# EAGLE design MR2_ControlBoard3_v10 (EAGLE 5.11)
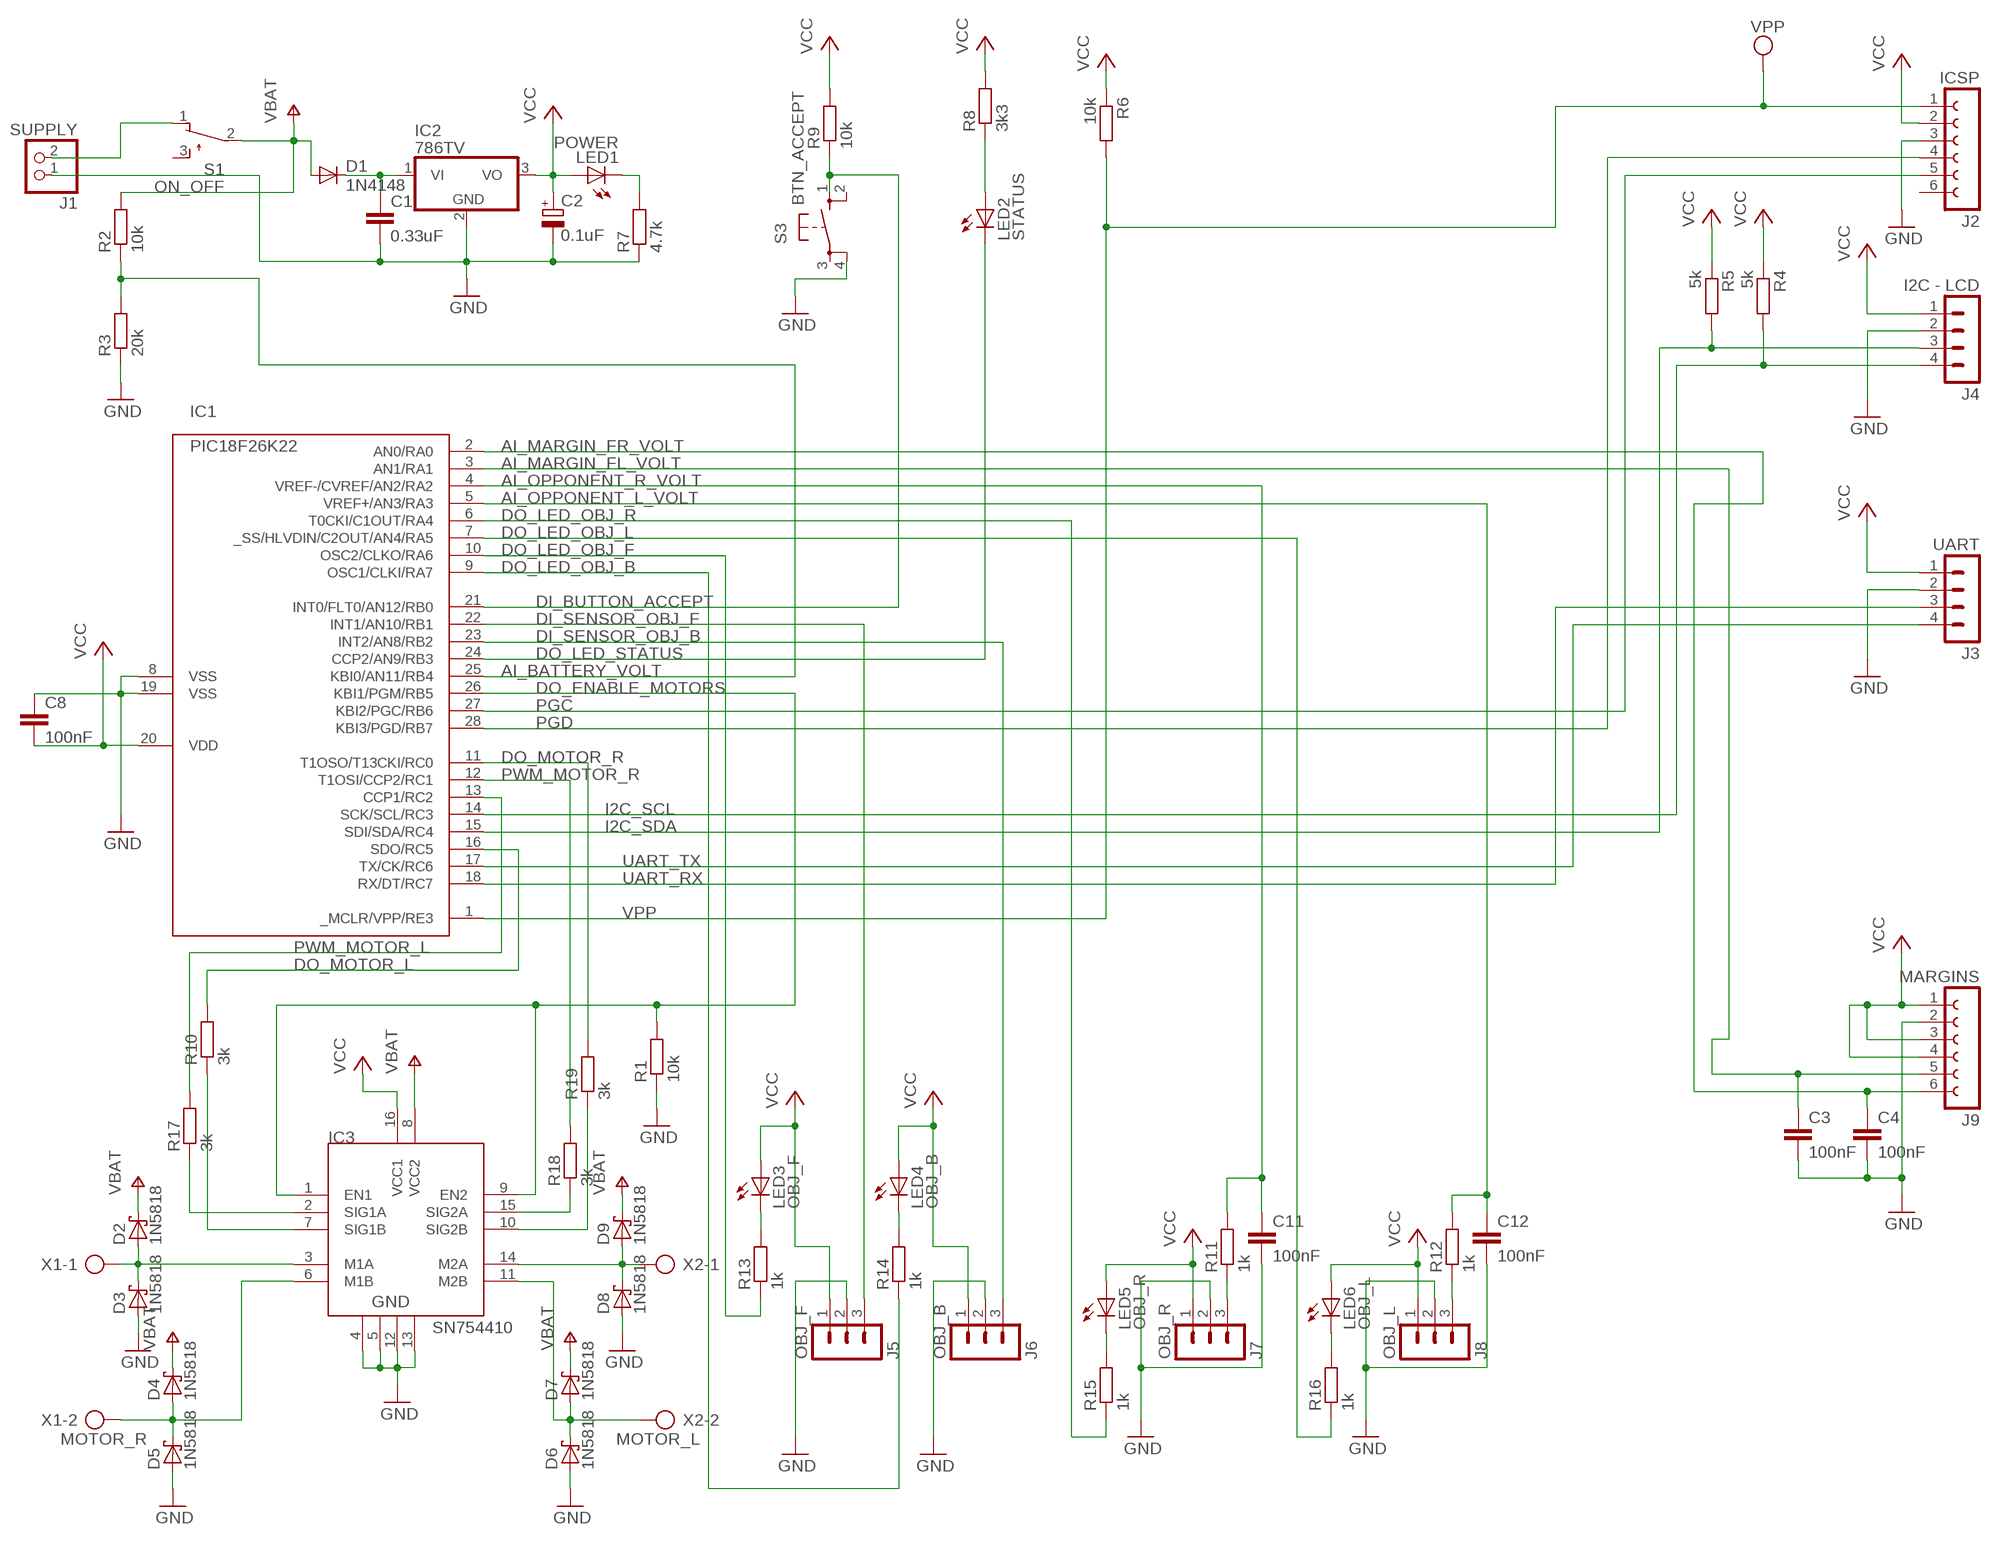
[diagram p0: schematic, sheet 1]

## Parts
C1  0.33uF  C-EU075-052X106  [C075-052X106]
C2  0.1uF  CPOL-EUE2,5-6E  [E2,5-6E]
C3  100nF  C-EU025-024X044  [C025-024X044]
C4  100nF  C-EU025-024X044  [C025-024X044]
C8  100nF  C-EU025-024X044  [C025-024X044]
C11  100nF  C-EU025-024X044  [C025-024X044]
C12  100nF  C-EU025-024X044  [C025-024X044]
D1  1N4148  1N4148DO35-7  [DO35-7]
D2  1N5818  1N5818-T  [DO41-7.6]
D3  1N5818  1N5818-T  [DO41-7.6]
D4  1N5818  1N5818-T  [DO41-7.6]
D5  1N5818  1N5818-T  [DO41-7.6]
D6  1N5818  1N5818-T  [DO41-7.6]
D7  1N5818  1N5818-T  [DO41-7.6]
D8  1N5818  1N5818-T  [DO41-7.6]
D9  1N5818  1N5818-T  [DO41-7.6]
IC1  PIC18F26K22  PIC18F2420-I/SP  [DIL28-3]
IC2  786TV  [TO220V]
IC3  SN754410  [DIP16]
J1  SUPPLY  PINHD-1X2  [1X02]
J2  ICSP  FE06-1  [FE06]
J3  UART  MA04-1  [MA04-1]
J4  I2C - LCD  MA04-1  [MA04-1]
J5  OBJ_F  MA03-1  [MA03-1]
J6  OBJ_B  MA03-1  [MA03-1]
J7  OBJ_R  MA03-1  [MA03-1]
J8  OBJ_L  MA03-1  [MA03-1]
J9  MARGINS  FE06-1  [FE06]
LED1  POWER  LED3MM  [LED3MM]
LED2  STATUS  LED3MM  [LED3MM]
LED3  OBJ_F  LED3MM  [LED3MM]
LED4  OBJ_B  LED3MM  [LED3MM]
LED5  OBJ_R  LED3MM  [LED3MM]
LED6  OBJ_L  LED3MM  [LED3MM]
R1  10k  R-EU_0204/7  [0204/7]
R2  10k  R-EU_0204/7  [0204/7]
R3  20k  R-EU_0204/7  [0204/7]
R4  5k  R-EU_0207/2V  [0207/2V]
R5  5k  R-EU_0207/2V  [0207/2V]
R6  10k  R-EU_0204/7  [0204/7]
R7  4.7k  R-EU_0204/7  [0204/7]
R8  3k3  R-EU_0204/7  [0204/7]
R9  10k  R-EU_0204/7  [0204/7]
R10  3k  R-EU_0204/7  [0204/7]
R11  1k  R-EU_0207/7  [0207/7]
R12  1k  R-EU_0207/7  [0207/7]
R13  1k  R-EU_0204/7  [0204/7]
R14  1k  R-EU_0204/7  [0204/7]
R15  1k  R-EU_0207/2V  [0207/2V]
R16  1k  R-EU_0207/2V  [0207/2V]
R17  3k  R-EU_0204/7  [0204/7]
R18  3k  R-EU_0204/7  [0204/7]
R19  3k  R-EU_0204/7  [0204/7]
S1  ON_OFF  TL32PO  [TL3XPO]
S3  BTN_ACCEPT  10XX  [B3F-10XX]
X1  MOTOR_R  AK500/2  [AK500/2]
X2  MOTOR_L  AK500/2  [AK500/2]

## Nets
AI_BATTERY_VOLT: IC1.25(KBI0/AN11/RB4) R2.1 R3.2
AI_MARGIN_FL_VOLT: C3.1 IC1.3(AN1/RA1) J9.5
AI_MARGIN_FR_VOLT: C4.1 IC1.2(AN0/RA0) J9.6
AI_OPPONENT_L_VOLT: C12.1 IC1.5(VREF+/AN3/RA3) R12.2
AI_OPPONENT_R_VOLT: C11.1 IC1.4(VREF-/CVREF/AN2/RA2) R11.2
DI_BUTTON_ACCEPT: IC1.21(INT0/FLT0/AN12/RB0) R9.1 S3.1
DI_SENSOR_OBJ_B: IC1.23(INT2/AN8/RB2) J6.3
DI_SENSOR_OBJ_F: IC1.22(INT1/AN10/RB1) J5.3
DO_ENABLE_MOTORS: IC1.26(KBI1/PGM/RB5) IC3.1(EN1) IC3.9(EN2) R1.2
DO_LED_OBJ_B: IC1.9(OSC1/CLKI/RA7) R14.1
DO_LED_OBJ_F: IC1.10(OSC2/CLKO/RA6) R13.1
DO_LED_OBJ_L: IC1.7(_SS/HLVDIN/C2OUT/AN4/RA5) R16.1
DO_LED_OBJ_R: IC1.6(T0CKI/C1OUT/RA4) R15.1
DO_LED_STATUS: IC1.24(CCP2/AN9/RB3) LED2.K(C)
DO_MOTOR_L: IC1.16(SDO/RC5) R10.2
DO_MOTOR_R: IC1.11(T1OSO/T13CKI/RC0) R19.2
GND: C1.2 C2.- C3.2 C4.2 C8.1 C11.2 C12.2 D3.A D5.A D6.A D8.A IC1.8(VSS) IC1.19(VSS) IC2.2(GND) IC3.4 IC3.5 IC3.12 IC3.13 J1.1 J2.3 J3.2 J4.2 J5.2 J6.2 J7.2 J8.2 J9.2 R1.1 R3.1 R7.1 S3.4
I2C_SCL: IC1.14(SCK/SCL/RC3) J4.4 R4.2
I2C_SDA: IC1.15(SDI/SDA/RC4) J4.3 R5.2
N$1: IC3.2(SIG1A) R17.1
N$2: C1.1 D1.C IC2.1(VI)
N$3: J7.3 R11.1
N$5: IC3.7(SIG1B) R10.1
N$6: LED1.K(C) R7.2
N$7: IC3.15(SIG2A) R18.1
N$8: IC3.10(SIG2B) R19.1
N$9: J1.2 S1.1(O)
N$13: LED3.K(C) R13.2
N$16: LED4.K(C) R14.2
N$18: LED5.K(C) R15.2
N$19: LED6.K(C) R16.2
N$21: LED2.A R8.1
N$27: D2.A D3.C IC3.3(M1A) X1.1
N$28: D4.A D5.C IC3.6(M1B) X1.2
N$29: D8.C D9.A IC3.14(M2A) X2.1
N$30: D6.C D7.A IC3.11(M2B) X2.2
N$41: J8.3 R12.1
PGC: IC1.27(KBI2/PGC/RB6) J2.5
PGD: IC1.28(KBI3/PGD/RB7) J2.4
PWM_MOTOR_L: IC1.13(CCP1/RC2) R17.2
PWM_MOTOR_R: IC1.12(T1OSI/CCP2/RC1) R18.2
UART_RX: IC1.18(RX/DT/RC7) J3.3
UART_TX: IC1.17(TX/CK/RC6) J3.4
V+: D1.A D2.C D4.C D7.C D9.C IC3.8(VCC2) R2.2 S1.2(P) ; supply symbol labelled VBAT
VCC: C2.+ C8.2 IC1.20(VDD) IC2.3(VO) IC3.16(VCC1) J2.2 J3.1 J4.1 J5.1 J6.1 J7.1 J8.1 J9.1 J9.3 J9.4 LED1.A LED3.A LED4.A LED5.A LED6.A R4.1 R5.1 R6.1 R8.2 R9.2
VPP: IC1.1(_MCLR/VPP/RE3) J2.1 R6.2
Unconnected: J2.6 S1.3(S) S3.2 S3.3

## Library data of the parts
C1 C3 C4 C8 C11 C12 = rcl:C-EU: CAPACITOR, European symbol
C2 = rcl:CPOL-EU: POLARIZED CAPACITOR, European symbol
D1 = diode:1N4148: DIODE
D2-D9 = diode:1N581*: 1.0A SCHOTTKY BARRIER RECTIFIER
IC1 = pic18fxx20:PIC18*2420: PIC18*2420 Microchip FLASH Microcontroller with A/D DEVICE FEATURES FeaturePIC18*2420 Program Memory (bytes) 16384 Program Memory (instructions) 8192 Interupt Sources 19 I/O Ports Ports A, B, C, (E) Capture/Compare/PWM Modules 2 Enhanced Capture/Compare/PWM Modules 0 Parallel Communications (PSP)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
IC2 = linear:78*: Positive VOLTAGE REGULATOR Source: http://cache.national.com/ds/LM/LM78L05.pdf http://www.fairchildsemi.com/ds/LM/LM7805.pdf
IC3 = HBridge:SN754410: Quadruple half-H driver
J1 = pinhead:PINHD-1X2: PIN HEADER
J2 J9 = con-lsta:FE06-1: FEMALE HEADER
J3 J4 = con-lstb:MA04-1: PIN HEADER
J5-J8 = con-lstb:MA03-1: PIN HEADER
LED1-LED6 = led:LED: LED
R1-R19 = rcl:R-EU_: RESISTOR, European symbol
S1 = switch:TL32PO: TINY SWITCH ON - MOM Source: http://www2.produktinfo.conrad.com/datenblaetter/700000-724999/705152-da-01-de-Subminiaturschalter_TL_36YO.pdf
S3 = KEY_B:10XX
X1 X2 = con-ptr500:AK500/2: CONNECTOR

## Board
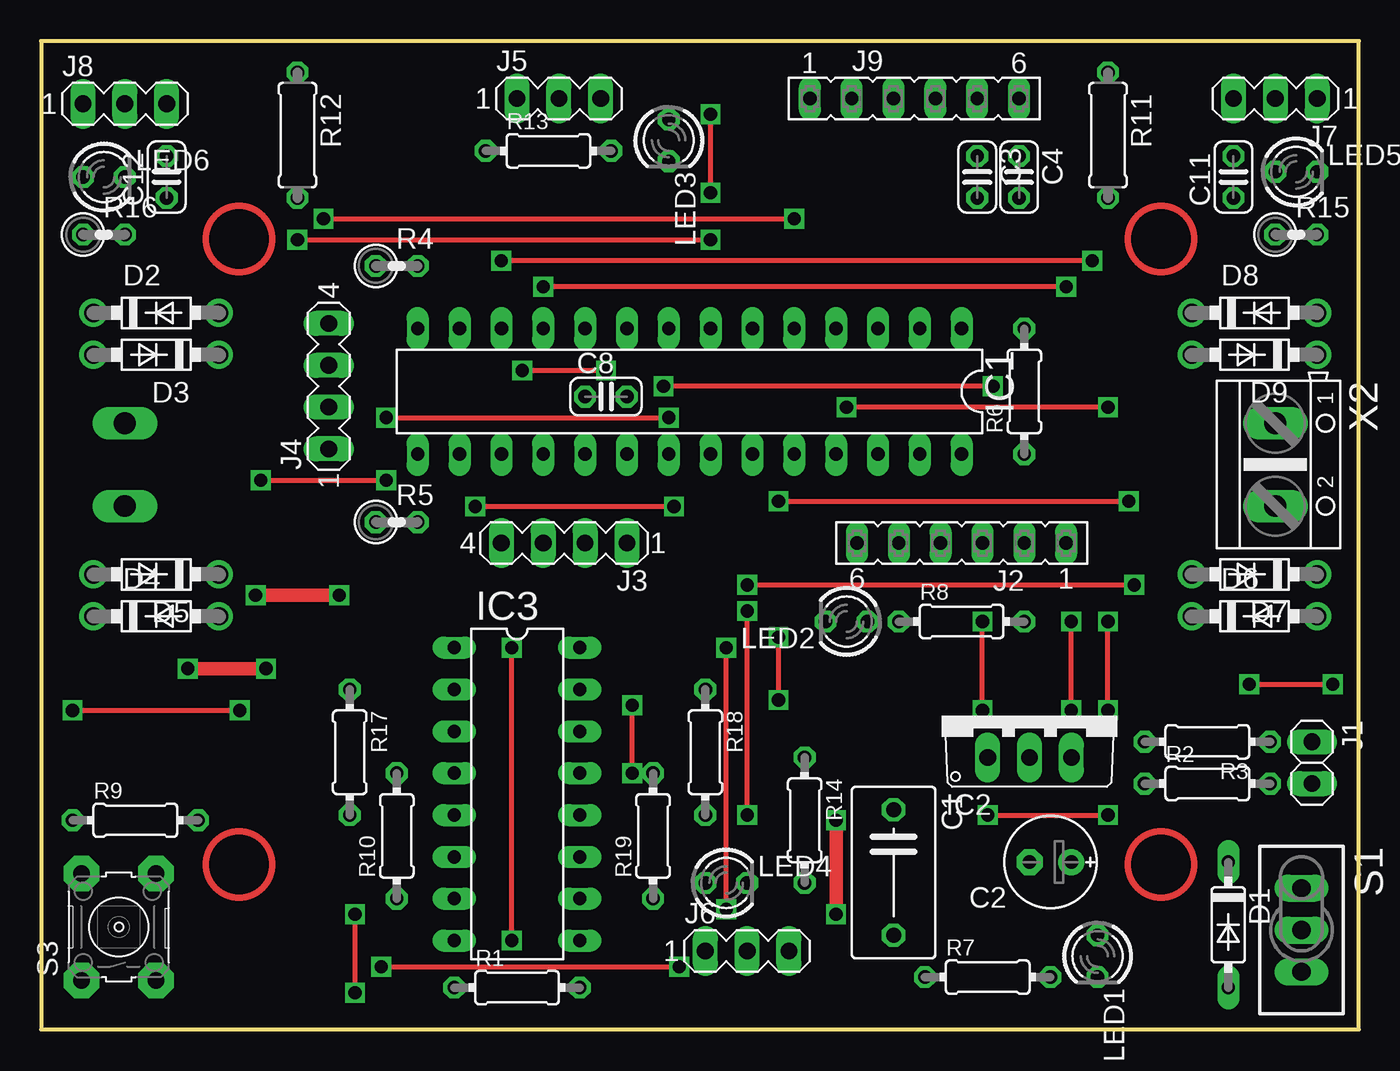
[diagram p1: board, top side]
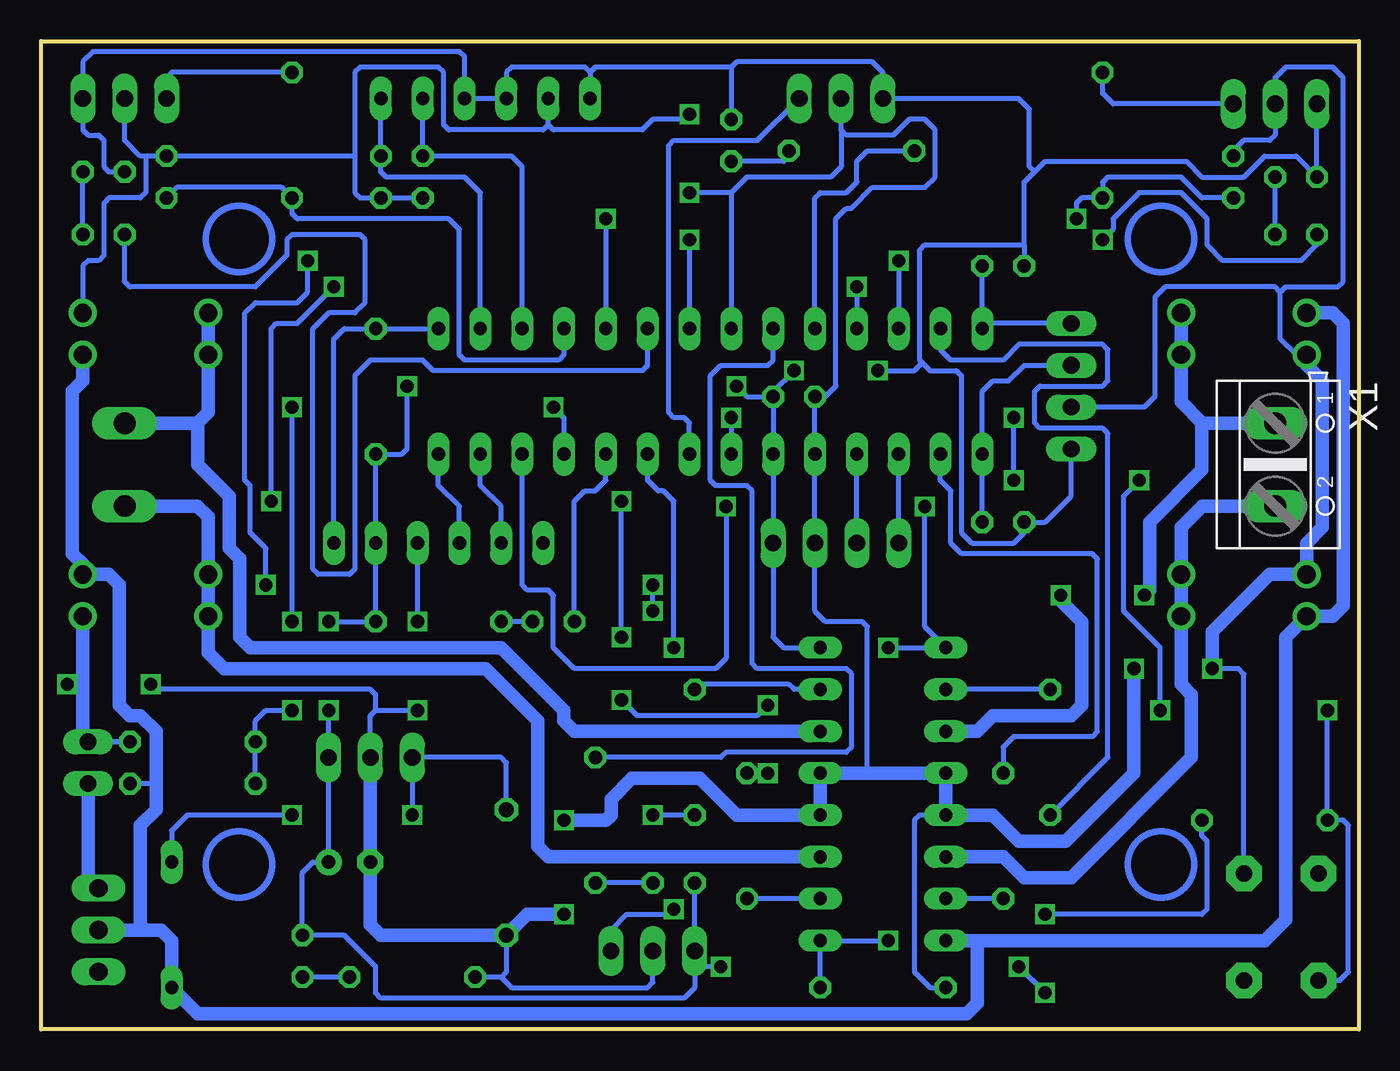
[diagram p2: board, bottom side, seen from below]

Size 80 x 60 mm. Coordinates in mm from the lower left corner, seen from the top.
Outline: 0,0 80,0 80,60 0,60 0,0
Copper layers (1*16): Top 0.035mm / dielectric 1.5mm / Bottom 0.035mm
Design rules "default *": minimum track width 12mil, minimum drill 24mil, track to track 12mil, track to pad 12mil, pad to pad 12mil, via to via 12mil, smd to smd 8mil, copper to edge 40mil, drill to drill 8mil, minimum pad ring 10mil, minimum via ring 8mil, stop-mask expansion 4mil, vias tented up to drill 0mil, thermal gap 10mil

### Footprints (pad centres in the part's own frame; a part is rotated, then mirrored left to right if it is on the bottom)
C075-052X106 = drill 0.914 octagon: 1 -3.81,0; 2 3.81,0
E2,5-6E = drill 0.813 pad 1.575 round: + -1.27,0 | drill 0.813 pad 1.575 octagon: - 1.27,0
C025-024X044 = drill 0.813 octagon: 1 -1.27,0; 2 1.27,0
DO35-7 = drill 0.813 long: A 3.81,0; C -3.81,0
DO41-7.6 = drill 1.1 pad 1.7 round: A 3.81,0; C -3.81,0
DIL28-3 = drill 0.813 long: 1 -16.51,-3.81; 2 -13.97,-3.81; 3 -11.43,-3.81; 4 -8.89,-3.81; 5 -6.35,-3.81; 6 -3.81,-3.81; 7 -1.27,-3.81; 8 1.27,-3.81; 9 3.81,-3.81; 10 6.35,-3.81; 11 8.89,-3.81; 12 11.43,-3.81; 13 13.97,-3.81; 14 16.51,-3.81; 15 16.51,3.81; 16 13.97,3.81; 17 11.43,3.81; 18 8.89,3.81; 19 6.35,3.81; 20 3.81,3.81; 21 1.27,3.81; 22 -1.27,3.81; 23 -3.81,3.81; 24 -6.35,3.81; 25 -8.89,3.81; 26 -11.43,3.81; 27 -13.97,3.81; 28 -16.51,3.81
TO220V = drill 1.016 long: 1 -2.54,-2.54; 2 0,-2.54; 3 2.54,-2.54
DIP16 = drill 0.813 long: 1 -10.16,-3.81; 2 -7.62,-3.81; 3 -5.08,-3.81; 4 -2.54,-3.81; 5 0,-3.81; 6 2.54,-3.81; 7 5.08,-3.81; 8 7.62,-3.81; 9 7.62,3.81; 10 5.08,3.81; 11 2.54,3.81; 12 0,3.81; 13 -2.54,3.81; 14 -5.08,3.81; 15 -7.62,3.81; 16 -10.16,3.81
1X02 = drill 1.016 long: 1 -1.27,0; 2 1.27,0
FE06 = drill 0.813 long: 1 -6.35,0; 2 -3.81,0; 3 -1.27,0; 4 1.27,0; 5 3.81,0; 6 6.35,0
MA04-1 = drill 1.016 long: 1 -3.81,0; 2 -1.27,0; 3 1.27,0; 4 3.81,0
MA03-1 = drill 1.016 long: 1 -2.54,0; 2 0,0; 3 2.54,0
LED3MM = drill 0.813 octagon: A -1.27,0; K 1.27,0
0204/7 = drill 0.813 octagon: 1 -3.81,0; 2 3.81,0
0207/2V = drill 0.813 octagon: 1 -1.27,0; 2 1.27,0
0207/7 = drill 0.813 octagon: 1 -3.81,0; 2 3.81,0
TL3XPO = drill 1.1 pad 1.422 long: 1 -2.54,0; 2 0,0; 3 2.54,0
B3F-10XX = drill 1.016 pad 2.159 octagon: 1 -3.379,2.312; 2 3.123,2.312; 3 -3.379,-2.209; 4 3.123,-2.209
AK500/2 = drill 1.321 long: 1 -2.515,0; 2 2.515,0

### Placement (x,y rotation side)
C1  51.75,9.53 270 top
C2  61.28,10.16 180 top
C3  56.83,51.75 270 top
C4  59.37,51.75 270 top
C8  34.29,38.42 0 top
C11  72.39,51.75 90 top
C12  7.62,51.75 90 top
D1  72.07,6.35 270 top
D2  6.99,43.5 0 top
D3  6.99,40.96 180 top
D4  6.99,25.08 0 top
D5  6.99,27.62 180 top
D6  73.66,25.08 0 top
D7  73.66,27.62 180 top
D8  73.66,43.5 0 top
D9  73.66,40.96 180 top
IC1  39.37,38.73 180 top
IC2  60.01,19.05 0 top
IC3  28.89,13.02 270 top
J1  77.15,16.19 270 top
J2  55.88,29.53 180 top
J3  31.75,29.53 180 top
J4  17.46,39.05 90 top
J5  31.43,56.52 0 top
J6  42.86,4.76 0 top
J7  74.93,56.52 180 top
J8  5.08,56.2 0 top
J9  53.02,56.52 0 top
LED1  64.14,4.45 270 top
LED2  48.9,24.77 180 top
LED3  38.1,53.98 270 top
LED4  41.59,8.89 0 top
LED5  76.2,52.07 0 top
LED6  3.81,51.75 0 top
R1  28.89,2.54 0 top
R2  70.8,14.92 0 top
R3  70.8,17.46 180 top
R4  21.59,46.35 0 top
R5  21.59,30.8 0 top
R6  59.69,38.73 90 top
R7  57.47,3.17 0 top
R8  55.88,24.77 0 top
R9  5.71,12.7 0 top
R10  21.59,11.75 90 top
R11  64.77,54.29 270 top
R12  15.56,54.29 270 top
R13  30.8,53.34 0 top
R14  46.35,12.7 270 top
R15  76.2,48.26 0 top
R16  3.81,48.26 0 top
R17  18.73,16.83 270 top
R18  40.32,16.83 270 top
R19  37.15,11.75 90 top
S1  76.52,6.03 270 top
S3  4.76,6.35 90 top
X1  5.08,34.29 270 bottom
X2  74.93,34.29 270 top

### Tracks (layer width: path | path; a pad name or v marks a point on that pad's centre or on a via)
AI_BATTERY_VOLT  (via drill 0.8)
  Top 0.305: v64.77,37.78 v48.9,37.78 | v64.77,19.37 v64.77,24.77
  Bottom 0.305: R2.1 R3.2 66.99,18.73 66.36,19.37 v64.77,19.37 | IC1.25 48.26,37.15 v48.9,37.78 | v64.77,24.77 v64.77,37.78
AI_MARGIN_FL_VOLT
  Bottom 0.305: J9.5 C3.1 51.44,53.02 50.8,52.39 IC1.3
AI_MARGIN_FR_VOLT
  Bottom 0.305: J9.6 C4.1 59.37,52.07 59.05,51.75 54.29,51.75 53.34,50.8 IC1.2
AI_OPPONENT_L_VOLT  (via drill 0.8)
  Top 0.305: v17.14,49.21 v45.72,49.21
  Bottom 0.305: v45.72,49.21 IC1.5 | v17.14,49.21 17.14,50.16 16.83,50.48 R12.2 15.56,51.44 15.24,51.75 10.79,51.75 9.53,50.48 C12.1
AI_OPPONENT_R_VOLT
  Bottom 0.305: C11.1 71.75,51.12 65.41,51.12 R11.2 64.77,49.53 64.45,49.21 55.24,49.21 54.61,48.58 54.61,40.96 54.29,40.64 48.58,40.64 48.26,40.96 IC1.4
DI_BUTTON_ACCEPT  (via drill 0.8)
  Top 0.305: v20.95,37.15 v38.1,37.15 | v1.91,19.37 v12.06,19.37 | v13.34,33.34 v20.95,33.34
  Bottom 0.305: S3.1 1.16,2.97 0.64,3.49 0.64,12.38 0.95,12.7 R9.1 v1.91,19.37 | v12.06,19.37 12.06,23.18 14.29,25.4 14.29,32.38 v13.34,33.34 | v20.95,33.34 v20.95,37.15 | v38.1,37.15 IC1.21
DI_SENSOR_OBJ_B  (via drill 0.8)
  Top 0.305: v41.59,7.3 v41.59,23.18
  Bottom 0.305: J6.3 45.4,6.03 44.45,6.99 41.91,6.99 v41.59,7.3 | v41.59,23.18 41.59,32.07 42.23,32.7 42.55,32.7 43.18,33.34 IC1.23
DI_SENSOR_OBJ_F
  Bottom 0.305: J5.3 36.51,53.98 41.59,53.98 41.91,53.66 41.91,37.47 41.59,37.15 40.96,37.15 40.64,36.83 IC1.22
DO_ENABLE_MOTORS  (via drill 0.8)
  Top 0.305: v28.57,5.4 v28.57,23.18 | v26.35,31.75 v38.42,31.75
  Bottom 0.305: R1.2 IC3.9 v28.57,5.4 | v28.57,23.18 IC3.1 26.35,24.45 v26.35,31.75 | IC1.26 50.8,26.99 50.48,26.67 49.21,26.67 48.9,26.35 48.9,23.18 47.62,21.91 39.05,21.91 38.42,22.54 v38.42,31.75
DO_LED_OBJ_B
  Bottom 0.305: R14.1 38.73,16.51 38.42,16.83 31.11,16.83 30.8,17.14 30.8,21.59 31.11,21.91 36.51,21.91 36.83,22.23 36.83,32.7 37.15,33.02 39.05,33.02 39.37,33.34 39.37,39.69 38.73,40.32 35.88,40.32 35.56,40.64 IC1.9
DO_LED_OBJ_F
  Bottom 0.305: R13.1 29.84,53.34 30.48,52.7 30.48,51.44 31.11,50.8 32.7,50.8 33.02,50.48 IC1.10
DO_LED_OBJ_L  (via drill 0.8)
  Top 0.305: v15.56,47.94 v40.64,47.94
  Bottom 0.305: R16.1 2.54,47.62 3.49,46.67 8.26,46.67 9.21,47.62 9.21,49.21 10.79,50.8 13.34,50.8 14.92,49.21 14.92,48.58 v15.56,47.94 | v40.64,47.94 IC1.7
DO_LED_OBJ_R
  Bottom 0.305: IC1.6 43.18,40.32 43.5,40.01 56.2,40.01 56.83,40.64 60.01,40.64 60.96,39.69 60.96,27.94 61.28,27.62 63.18,27.62 63.5,27.94 63.5,42.55 62.55,43.5 60.96,43.5 60.33,44.13 60.33,47.94 60.64,48.26 64.77,48.26 65.09,47.94 65.09,46.99 66.99,45.09 74.61,45.09 74.93,45.4 R15.1
DO_LED_STATUS
  Bottom 0.305: LED2.K 47.62,32.07 46.99,32.7 46.35,32.7 45.72,33.34 IC1.24
DO_MOTOR_L
  Bottom 0.305: R10.2 21.59,17.14 20.95,17.78 16.19,17.78 15.88,18.1 15.88,28.57 16.19,28.89 24.13,28.89 24.77,29.53 24.77,32.7 25.4,33.34 IC1.16
DO_MOTOR_R  (via drill 0.8)
  Top 0.305: v62.23,45.09 v30.48,45.09 | v44.77,32.07 v66.04,32.07 | v44.77,20 v44.77,23.81 | v35.88,15.56 v35.88,19.68
  Bottom 0.305: v30.48,45.09 IC1.11 | v62.23,45.09 64.45,42.86 65.72,42.86 66.04,42.55 v66.04,32.07 | v44.77,23.81 v44.77,32.07 | R19.2 v35.88,15.56 | v44.77,20 43.81,19.05 36.51,19.05 v35.88,19.68
GND  (via drill 0.8)
  Top 0.305: v57.15,19.37 v57.15,24.77 | v73.34,20.95 v78.42,20.95 | v40.64,50.8 v40.64,55.56
  Top 0.813: v8.89,21.91 v13.65,21.91 | v48.26,12.7 v48.26,6.99
  Bottom 0.305: R1.1 26.04,2.54 26.99,3.49 26.99,12.7 26.67,13.02 IC3.5 | C3.2 C4.2 60.64,50.48 60.96,50.8 60.96,53.02 | 49.21,54.93 J9.2 | 49.21,54.93 49.53,54.61 55.24,54.61 55.56,54.93 55.56,58.1 55.88,58.42 60.64,58.42 60.96,58.1 60.96,53.02 | J7.2 74.93,53.98 73.98,53.02 73.66,53.02 | 73.66,53.02 C11.2 60.96,53.02 | D8.A 77.47,46.35 77.15,46.67 76.52,46.67 76.2,46.99 76.2,50.16 75.88,50.48 73.98,50.48 73.66,50.8 73.66,53.02 | D3.A 3.81,40.96 4.76,41.91 4.76,44.77 | C12.2 7.62,53.34 6.99,53.98 5.4,53.98 5.08,54.29 J8.2 5.08,57.78 4.45,58.42 1.59,58.42 0.95,57.78 0.95,45.4 1.27,45.09 4.45,45.09 4.76,44.77 | 52.07,3.17 R7.1 | 52.07,3.17 51.75,3.49 C1.2 | J6.2 42.86,2.86 43.18,2.54 51.44,2.54 52.07,3.17 | v57.15,24.77 J2.3 | 59.69,19.37 v57.15,19.37 | 59.69,19.37 60.01,19.05 IC2.2 | J1.1 R3.1 77.47,17.46 77.47,20.64 77.79,20.95 v78.42,20.95 | 4.76,44.77 5.08,45.09 11.75,45.09 12.38,44.45 12.38,38.42 13.02,37.78 J4.2 | 31.43,54.61 31.43,52.39 32.07,51.75 37.15,51.75 38.1,50.8 | 31.43,54.61 J5.2 | 38.1,50.8 IC1.8 | 49.21,54.93 48.9,54.61 43.5,54.61 42.86,55.24 40.96,55.24 v40.64,55.56 | 38.1,50.8 v40.64,50.8 | 29.84,15.56 29.84,24.45 30.16,24.77 32.38,24.77 33.02,25.4 J3.2 IC1.19 C8.1 32.38,38.42 31.75,39.05 31.75,49.21 31.11,49.85 30.8,49.85 29.53,51.12 26.35,51.12 25.72,51.75 25.72,54.61 26.35,55.24 27.3,55.24 28.26,54.29 31.11,54.29 31.43,54.61 | S3.4 6.97,21.58 7.3,21.91 v8.89,21.91 | 59.69,19.37 59.69,20.32 60.01,20.64 73.03,20.64 v73.34,20.95
  Bottom 0.813: D6.A 77.47,17.78 J1.1 | D3.A 3.17,40.32 2.22,39.37 2.22,30.48 3.17,29.53 D5.A 5.4,27.62 8.89,24.13 v8.89,21.91 | IC2.2 C2.- 60.01,6.35 59.37,5.71 C1.2 50.48,6.99 v48.26,6.99 | v13.65,21.91 13.65,15.56 17.78,11.43 20.64,11.43 22.23,13.02 IC3.5 IC3.4 29.84,15.56 IC3.13 IC3.12 37.78,13.02 40.01,15.24 44.13,15.24 45.4,13.97 45.4,13.02 45.72,12.7 v48.26,12.7
I2C_SCL
  Bottom 0.305: J4.4 22.54,42.86 IC1.14 R4.2
I2C_SDA
  Bottom 0.305: R5.2 IC1.15 22.86,38.73 22.23,39.37 21.27,39.37 20.32,40.32 J4.3
N$1
  Bottom 0.305: R17.1 IC3.2
N$2  (via drill 0.8)
  Top 0.305: v57.47,13.02 v64.77,13.02
  Bottom 0.305: C1.1 51.75,16.19 52.07,16.51 IC2.1 v57.47,13.02 | D1.C 72.07,12.06 71.12,13.02 v64.77,13.02
N$3
  Bottom 0.305: R11.1 72.07,58.1 72.39,57.78 J7.3
N$5
  Bottom 0.305: R10.1 IC3.7
N$6
  Bottom 0.305: R7.2 LED1.K
N$7
  Bottom 0.305: IC3.15 34.29,20.64 34.61,20.95 40.01,20.95 R18.1
N$8
  Bottom 0.305: IC3.10 R19.1
N$9
  Bottom 0.813: J1.2 77.15,9.21 S1.1
N$13
  Bottom 0.305: R13.2 34.61,53.02 34.92,52.7 LED3.K
N$16
  Bottom 0.305: LED4.K R14.2
N$18
  Bottom 0.305: R15.2 LED5.K
N$19
  Bottom 0.305: R16.2 LED6.K
N$21
  Bottom 0.305: LED2.A R8.1
N$27  (via drill 0.8)
  Top 0.813: v18.1,26.35 v13.02,26.35
  Bottom 0.813: D2.A D3.C 10.79,38.1 9.53,36.83 | X1.1 9.5,36.8 9.53,36.83 | 9.53,36.83 9.53,33.97 12.7,30.8 12.7,26.67 v13.02,26.35 | v18.1,26.35 18.1,26.04 16.83,24.77 16.83,19.68 17.46,19.05 22.23,19.05 23.18,18.1 IC3.3
N$28
  Bottom 0.813: X1.2 9.5,31.77 10.79,30.48 D5.C D4.A 10.79,20.95 10.16,20.32 10.16,16.51 17.46,9.21 20.32,9.21 21.59,10.48 IC3.6
N$29
  Bottom 0.813: 70.51,36.8 X2.1 | 70.51,36.8 69.85,37.47 D9.A D8.C | IC3.14 47.62,18.1 48.26,18.73 48.26,19.37 52.07,23.18 67.31,23.18 67.94,23.81 67.94,28.57 68.58,29.21 68.58,32.38 70.48,34.29 70.48,36.78 70.51,36.8
N$30
  Bottom 0.813: X2.2 70.51,31.77 69.85,31.11 D7.A D6.C 69.85,22.86 68.9,21.91 53.02,21.91 49.85,18.73 49.85,11.11 49.21,10.48 IC3.11
N$41
  Bottom 0.305: J8.3 14.92,56.2 15.56,56.83 R12.1
PGC
  Bottom 0.305: J2.5 52.07,31.75 53.34,33.02 IC1.27
PGD
  Bottom 0.305: J2.4 54.61,31.75 55.88,33.02 IC1.28
PWM_MOTOR_L
  Bottom 0.305: IC1.13 25.4,41.27 24.77,40.64 21.59,40.64 20.64,41.59 15.56,41.59 15.24,41.27 15.24,39.37 15.56,39.05 19.37,39.05 19.68,38.73 19.68,36.83 19.37,36.51 15.56,36.51 15.24,36.2 15.24,16.51 R17.2
PWM_MOTOR_R  (via drill 0.8)
  Top 0.305: v63.82,46.67 v27.94,46.67 | v42.86,13.02 v42.86,25.4 | v42.86,26.99 v66.36,26.99
  Bottom 0.305: v27.94,46.67 IC1.12 | v63.82,46.67 63.82,44.77 64.45,44.13 66.99,44.13 67.63,43.5 67.63,33.34 67.31,33.02 67.31,30.16 66.36,29.21 v66.36,26.99 | R18.2 v42.86,13.02 | v42.86,25.4 v42.86,26.99
UART_RX
  Bottom 0.305: J3.3 IC1.18
UART_TX
  Bottom 0.305: J3.4 IC1.17
V+
  Bottom 0.305: 73.03,14.92 R2.2
  Bottom 0.813: D9.C 77.47,39.37 78.11,38.73 78.11,28.89 77.47,28.26 D7.C 75.88,27.62 75.25,26.99 75.25,19.68 74.61,19.05 73.98,19.05 73.03,18.1 73.03,14.92 73.03,13.34 73.98,12.38 73.98,6.35 73.66,6.03 | 73.66,6.03 72.71,6.03 72.07,5.4 D1.A 70.48,0.95 23.81,0.95 23.18,1.59 23.18,5.4 | 73.66,6.03 S1.2 | D2.C 1.59,43.5 0.95,42.86 0.95,25.72 1.59,25.08 D4.C 4.45,23.81 4.45,6.67 5.71,5.4 23.18,5.4 | 23.18,5.4 IC3.8
VCC  (via drill 0.8)
  Top 0.305: v62.55,19.37 v62.55,24.77 | v57.78,39.05 v37.78,39.05 | v19.05,6.99 v19.05,2.22 | v20.64,3.81 v38.73,3.81 | v34.29,40.01 v29.21,40.01
  Bottom 0.305: J4.1 17.46,32.38 19.05,30.8 R5.1 20.32,30.16 20.95,29.53 23.5,29.53 24.13,30.16 24.13,39.69 24.45,40.01 26.04,40.01 26.51,40.48 | 46.67,58.1 46.99,58.42 51.44,58.42 51.75,58.1 J9.3 J9.4 54.29,59.05 54.61,59.37 76.83,59.37 77.47,58.74 J7.1 77.47,54.61 77.15,54.29 76.52,54.29 76.2,53.98 76.2,52.39 75.88,52.07 LED5.A | 46.67,58.1 J9.1 | 38.1,58.42 46.35,58.42 46.67,58.1 | 38.1,58.42 LED3.A | LED4.A J6.1 40.32,3.81 | J8.1 LED6.A 3.81,53.02 5.71,53.02 6.99,51.75 9.53,51.75 10.48,52.7 19.05,52.7 19.68,52.07 | 19.68,52.07 20.32,51.44 20.32,47.62 | 20.32,47.62 R4.1 | 19.68,52.07 20,52.39 20,55.88 20.64,56.52 J5.1 28.89,58.1 29.53,58.74 37.78,58.74 38.1,58.42 | 40.32,3.81 40.32,2.54 40.96,1.91 59.37,1.91 59.69,2.22 59.69,3.81 61.59,5.71 LED1.A 64.14,9.53 63.5,10.16 C2.+ IC2.3 v62.55,19.37 | IC3.16 34.92,23.18 35.56,23.81 J3.1 IC1.20 C8.2 | v62.55,24.77 R8.2 J2.2 R6.1 58.1,34.92 57.78,35.24 v57.78,39.05 | 26.51,40.48 26.67,40.64 26.67,47.31 26.35,47.62 20.32,47.62 | v19.05,6.99 9.53,6.99 9.21,7.3 9.21,11.43 9.53,11.75 9.53,12.06 | v19.05,2.22 v20.64,3.81 | v38.73,3.81 40.32,3.81 | C8.2 37.15,38.42 v37.78,39.05 | C8.2 35.56,38.73 v34.29,40.01 | v29.21,40.01 26.99,40.01 26.51,40.48
  Bottom 0.406: 9.53,12.06 R9.2
VPP
  Bottom 0.305: IC1.1 R6.2 61.59,42.55 62.23,41.91 J2.1
(copper drawn outside any net)
  shapes: Bottom circle x4, Top circle x4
